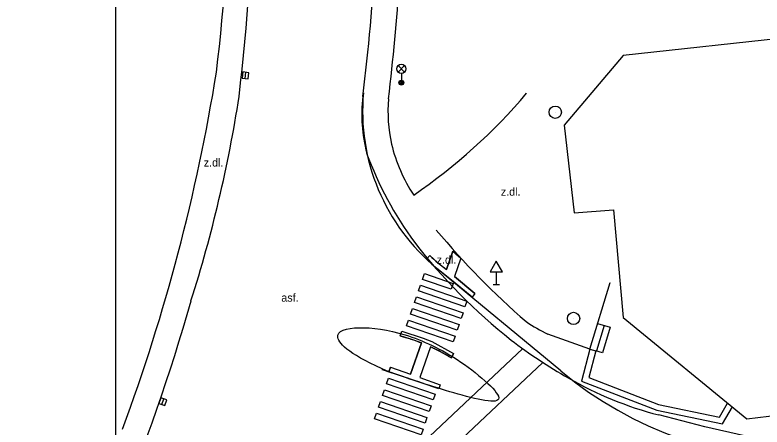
# Model space of a CAD drawing. Extents: x -438200 to -437954, y -1133133 to -1132850.
# Drawn here: x -438175.3 to -438114.6, y -1132947 to -1132913.5 of the extents above; entities that cross this region are included whole.
import ezdxf

# ---------------------------------------------------------------- set-up
doc = ezdxf.new("R2010")
doc.units = 0
for name, color, linetype in [('Vrstva 1', 7, 'Continuous'), ('Vrstva 10', 7, 'Continuous'), ('Vrstva 11', 7, 'Continuous'), ('Vrstva 15', 7, 'Continuous'), ('Vrstva 27', 7, 'Continuous'), ('Vrstva 33', 7, 'Continuous'), ('Vrstva 34', 7, 'Continuous'), ('Vrstva 40', 7, 'Continuous'), ('Vrstva 5', 7, 'Continuous'), ('Vrstva 7', 7, 'Continuous')]:
    doc.layers.add(name, color=color, linetype=linetype)

msp = doc.modelspace()

# ---------------------------------------------------------------- linework, layer by layer
at = {"layer": 'Vrstva 1'}
for p, q in [((-438167.156, -1132895.77), (-438167.156, -1133045.77)), ((-438167.156, -1132895.77), (-438167.156, -1133045.77)), ((-438158.957, -1132918.149), (-438158.957, -1132918.149)), ((-438156.595, -1132918.413), (-438156.595, -1132918.413)), ((-438143.939, -1132919.006), (-438143.939, -1132919.006)), ((-438157.116, -1132920.127), (-438157.116, -1132920.127)), ((-438147.07, -1132920.136), (-438147.07, -1132920.136)), ((-438133.765, -1132919.871), (-438133.765, -1132919.871)), ((-438144.985, -1132920.316), (-438144.985, -1132920.316)), ((-438131.431, -1132921.405), (-438131.431, -1132921.405)), ((-438130.7, -1132922.46), (-438130.7, -1132922.46)), ((-438144.742, -1132924.002), (-438144.742, -1132924.002)), ((-438137.844, -1132924.111), (-438137.844, -1132924.111)), ((-438146.757, -1132924.735), (-438146.757, -1132924.735)), ((-438142.935, -1132928.139), (-438142.935, -1132928.139)), ((-438126.705, -1132929.331), (-438126.705, -1132929.331)), ((-438144.335, -1132929.862), (-438144.335, -1132929.862)), ((-438129.914, -1132929.587), (-438129.914, -1132929.587)), ((-438141.101, -1132930.989), (-438141.101, -1132930.989)), ((-438142.882, -1132931.977), (-438142.882, -1132931.977)), ((-438130.987, -1132942.441), (-438141.071, -1132934.08)), ((-438130.987, -1132942.441), (-438141.071, -1132934.08)), ((-438136.224, -1132935.407), (-438136.224, -1132935.407)), ((-438126.979, -1132935.245), (-438126.979, -1132935.245)), ((-438139.671, -1132935.704), (-438139.671, -1132935.704)), ((-438136.973, -1132935.488), (-438136.973, -1132935.488)), ((-438161.028, -1132936.751), (-438161.028, -1132936.751)), ((-438133.787, -1132938.432), (-438133.787, -1132938.432)), ((-438129.95, -1132938.171), (-438129.95, -1132938.171)), ((-438125.927, -1132938.095), (-438125.927, -1132938.095)), ((-438126.976, -1132938.888), (-438126.976, -1132938.888)), ((-438132.039, -1132939.452), (-438132.039, -1132939.452)), ((-438135.02, -1132939.927), (-438135.02, -1132939.927)), ((-438128.639, -1132940.673), (-438128.639, -1132940.673)), ((-438130.379, -1132943.006), (-438130.379, -1132943.006)), ((-438129.292, -1132943.274), (-438129.292, -1132943.274)), ((-438163.315, -1132944.939), (-438163.315, -1132944.939)), ((-438127.076, -1132944.653), (-438127.076, -1132944.653)), ((-438123.197, -1132945.641), (-438123.197, -1132945.641)), ((-438123.021, -1132946.022), (-438123.021, -1132946.022)), ((-438115.881, -1132946.325), (-438115.881, -1132946.325)), ((-438117.845, -1132946.752), (-438117.845, -1132946.752)), ((-438119.29, -1132946.982), (-438119.29, -1132946.982))]:
    msp.add_line(p, q, dxfattribs=at)
for points in [[(-438139.753, -1132932.7), (-438139.103, -1132933.269), (-438139.616, -1132934.766), (-438137.962, -1132936.138), (-438138.18, -1132936.454), (-438139.738, -1132935.172), (-438141.071, -1132934.08), (-438141.908, -1132933.364), (-438141.626, -1132933.057), (-438140.995, -1132933.635), (-438140.269, -1132934.203)], [(-438139.753, -1132932.7), (-438139.103, -1132933.269), (-438139.616, -1132934.766), (-438137.962, -1132936.138), (-438138.18, -1132936.454), (-438139.738, -1132935.172), (-438141.071, -1132934.08), (-438141.908, -1132933.364), (-438141.626, -1132933.057), (-438140.995, -1132933.635), (-438140.269, -1132934.203)], [(-438142.23, -1132934.996), (-438142.068, -1132934.524), (-438139.738, -1132935.323), (-438139.901, -1132935.796)], [(-438142.23, -1132934.996), (-438142.068, -1132934.524), (-438139.738, -1132935.323), (-438139.901, -1132935.796)], [(-438142.555, -1132935.942), (-438142.393, -1132935.469), (-438138.612, -1132936.767), (-438138.775, -1132937.24)], [(-438142.555, -1132935.942), (-438142.393, -1132935.469), (-438138.612, -1132936.767), (-438138.775, -1132937.24)], [(-438142.879, -1132936.888), (-438142.717, -1132936.415), (-438138.926, -1132937.716), (-438139.089, -1132938.189)], [(-438142.879, -1132936.888), (-438142.717, -1132936.415), (-438138.926, -1132937.716), (-438139.089, -1132938.189)], [(-438143.204, -1132937.834), (-438143.042, -1132937.361), (-438139.242, -1132938.665), (-438139.404, -1132939.138)], [(-438143.204, -1132937.834), (-438143.042, -1132937.361), (-438139.242, -1132938.665), (-438139.404, -1132939.138)], [(-438143.529, -1132938.78), (-438143.366, -1132938.307), (-438139.564, -1132939.612), (-438139.727, -1132940.085)], [(-438143.529, -1132938.78), (-438143.366, -1132938.307), (-438139.564, -1132939.612), (-438139.727, -1132940.085)], [(-438145.149, -1132943.501), (-438144.986, -1132943.028), (-438141.204, -1132944.326), (-438141.366, -1132944.799)], [(-438145.149, -1132943.501), (-438144.986, -1132943.028), (-438141.204, -1132944.326), (-438141.366, -1132944.799)], [(-438145.473, -1132944.446), (-438145.311, -1132943.973), (-438141.529, -1132945.271), (-438141.691, -1132945.744)], [(-438145.473, -1132944.446), (-438145.311, -1132943.973), (-438141.529, -1132945.271), (-438141.691, -1132945.744)], [(-438145.798, -1132945.392), (-438145.636, -1132944.919), (-438141.856, -1132946.217), (-438142.018, -1132946.689)], [(-438145.798, -1132945.392), (-438145.636, -1132944.919), (-438141.856, -1132946.217), (-438142.018, -1132946.689)], [(-438146.122, -1132946.338), (-438145.96, -1132945.865), (-438142.177, -1132947.163), (-438142.339, -1132947.636)], [(-438146.122, -1132946.338), (-438145.96, -1132945.865), (-438142.177, -1132947.163), (-438142.339, -1132947.636)]]:
    msp.add_lwpolyline(points, close=True, dxfattribs=at)
for centre, radius, start, end in [((-438130.547, -1132921.319), 16.541, 174.80144, 230.49079), ((-438130.547, -1132921.319), 16.541, 174.80144, 230.49079), ((-438110.563, -1132917.807), 32, 230.33647, 309.11864), ((-438110.563, -1132917.807), 32, 230.33647, 309.11864)]:
    msp.add_arc(centre, radius, start, end, dxfattribs=at)
msp.add_open_spline([(-438144.958, -1132942.509), (-438148, -1132941.199), (-438149.996, -1132939.359), (-438147.626, -1132938.737), (-438143.739, -1132939.25), (-438139.185, -1132941.338), (-438134.209, -1132945.715), (-438140.218, -1132944.135), (-438144.958, -1132942.509), (-438146.526, -1132941.975), (-438142.582, -1132943.306)], degree=3, dxfattribs=at)
msp.add_open_spline([(-438144.958, -1132942.509), (-438148, -1132941.199), (-438149.996, -1132939.359), (-438147.626, -1132938.737), (-438143.739, -1132939.25), (-438139.185, -1132941.338), (-438134.209, -1132945.715), (-438140.218, -1132944.135), (-438144.958, -1132942.509), (-438146.526, -1132941.975), (-438142.582, -1132943.306)], degree=3, dxfattribs=at)
at = {"layer": 'Vrstva 10'}
for p, q in [((-438134.081, -1132940.629), (-438141.651, -1132947.764)), ((-438132.454, -1132941.746), (-438139.469, -1132948.358))]:
    msp.add_line(p, q, dxfattribs=at)
msp.add_lwpolyline([(-438095.924, -1132946.534), (-438105.196, -1132947.647), (-438110.044, -1132947.938), (-438116.055, -1132947.713), (-438119.29, -1132946.982), (-438123.021, -1132946.022)], dxfattribs=at)
for centre, radius, start, end in [((-438384.633, -1132894.507), 228.955, 353.57529, 2.49989), ((-438319.386, -1132898.79), 173.633, 352.93848, 0.58519), ((-438267.774, -1132902.859), 111.997, 342.38526, 351.13063), ((-438134.402, -1132921.584), 12.75, 173.47891, 194.30798), ((-438118.671, -1132914.365), 29.94, 200.26603, 216.03406), ((-438106.646, -1132904.004), 45.777, 217.66642, 231.69584), ((-438304.45, -1132896.337), 149.008, 330.05849, 344.26304), ((-438111.102, -1132908.912), 39.167, 232.36119, 240.51546), ((-438115.759, -1132917.821), 29.121, 239.86409, 255.55905)]:
    msp.add_arc(centre, radius, start, end, dxfattribs=at)
at = {"layer": 'Vrstva 11'}
for p, q in [((-438127.454, -1132938.742), (-438128.087, -1132940.815)), ((-438127.998, -1132938.576), (-438126.976, -1132938.888)), ((-438126.976, -1132938.888), (-438127.609, -1132940.961)), ((-438127.609, -1132940.961), (-438128.154, -1132940.795))]:
    msp.add_line(p, q, dxfattribs=at)
for points in [[(-438128.639, -1132940.673), (-438126.979, -1132935.245)], [(-438128.639, -1132940.673), (-438132.039, -1132939.452)]]:
    msp.add_lwpolyline(points, dxfattribs=at)
for centre, radius, start, end in [((-438353.312, -1132895.52), 195.668, 353.35896, 3.21989), ((-438315.621, -1132899.594), 171.89, 353.07606, 359.53813), ((-438312.067, -1132893.395), 155.099, 339.71616, 350.81615), ((-438168.696, -1132890.349), 45.735, 304.28128, 319.79662), ((-438132.457, -1132921.341), 12.57, 175.32209, 192.22146), ((-438132.131, -1132920.957), 12.973, 193.57537, 213.61507), ((-438092.402, -1132890.449), 63.365, 219.77595, 229.22236), ((-438125.547, -1132926.319), 14.65, 235.77473, 243.6961)]:
    msp.add_arc(centre, radius, start, end, dxfattribs=at)
at = {"layer": 'Vrstva 15'}
for p, q in [((-438139.753, -1132932.7), (-438140.269, -1132934.203)), ((-438139.753, -1132932.7), (-438140.269, -1132934.203)), ((-438141.626, -1132933.057), (-438141.908, -1132933.364)), ((-438141.626, -1132933.057), (-438141.908, -1132933.364)), ((-438139.103, -1132933.269), (-438139.616, -1132934.766)), ((-438139.103, -1132933.269), (-438139.616, -1132934.766)), ((-438137.962, -1132936.138), (-438139.616, -1132934.766)), ((-438137.962, -1132936.138), (-438139.616, -1132934.766)), ((-438137.962, -1132936.138), (-438138.18, -1132936.454)), ((-438137.962, -1132936.138), (-438138.18, -1132936.454)), ((-438144.026, -1132939.587), (-438143.892, -1132939.205)), ((-438144.026, -1132939.587), (-438143.892, -1132939.205)), ((-438142.312, -1132940.16), (-438143.188, -1132942.714)), ((-438142.312, -1132940.16), (-438143.188, -1132942.714)), ((-438141.574, -1132940.473), (-438142.434, -1132942.982)), ((-438141.574, -1132940.473), (-438142.434, -1132942.982)), ((-438139.864, -1132941.388), (-438139.696, -1132941.026)), ((-438139.864, -1132941.388), (-438139.696, -1132941.026)), ((-438144.829, -1132942.13), (-438144.958, -1132942.509)), ((-438144.829, -1132942.13), (-438144.958, -1132942.509)), ((-438144.829, -1132942.13), (-438143.188, -1132942.714)), ((-438144.829, -1132942.13), (-438143.188, -1132942.714)), ((-438142.434, -1132942.982), (-438140.785, -1132943.569)), ((-438142.434, -1132942.982), (-438140.785, -1132943.569)), ((-438140.785, -1132943.569), (-438140.891, -1132943.898)), ((-438140.785, -1132943.569), (-438140.891, -1132943.898))]:
    msp.add_line(p, q, dxfattribs=at)
msp.add_lwpolyline([(-438143.892, -1132939.205), (-438142.172, -1132939.775), (-438141.455, -1132940.057), (-438139.696, -1132941.026), (-438139.864, -1132941.388), (-438140.801, -1132940.849), (-438141.574, -1132940.473), (-438142.434, -1132942.982), (-438140.785, -1132943.569), (-438140.891, -1132943.898), (-438144.958, -1132942.509), (-438144.829, -1132942.13), (-438143.188, -1132942.714), (-438142.312, -1132940.16), (-438143.181, -1132939.847), (-438144.026, -1132939.587)], close=True, dxfattribs=at)
msp.add_lwpolyline([(-438143.892, -1132939.205), (-438142.172, -1132939.775), (-438141.455, -1132940.057), (-438139.696, -1132941.026), (-438139.864, -1132941.388), (-438140.801, -1132940.849), (-438141.574, -1132940.473), (-438142.434, -1132942.982), (-438140.785, -1132943.569), (-438140.891, -1132943.898), (-438144.958, -1132942.509), (-438144.829, -1132942.13), (-438143.188, -1132942.714), (-438142.312, -1132940.16), (-438143.181, -1132939.847), (-438144.026, -1132939.587)], close=True, dxfattribs=at)
for centre, start, end in [((-438128.804, -1132920.841), 227.28625, 230.3548), ((-438128.804, -1132920.841), 227.28625, 230.3548), ((-438130.547, -1132921.319), 226.65396, 232.96535), ((-438130.547, -1132921.319), 226.65396, 232.96535)]:
    msp.add_arc(centre, 16.141, start, end, dxfattribs=at)
for points, degree in [([(-438144.026, -1132939.587), (-438143.967, -1132939.604), (-438143.393, -1132939.773), (-438142.832, -1132939.956), (-438142.312, -1132940.16)], 3), ([(-438144.026, -1132939.587), (-438143.967, -1132939.604), (-438143.393, -1132939.773), (-438142.832, -1132939.956), (-438142.312, -1132940.16)], 3), ([(-438141.574, -1132940.473), (-438141.039, -1132940.717), (-438140.478, -1132941.013), (-438139.864, -1132941.388)], 2), ([(-438141.574, -1132940.473), (-438141.039, -1132940.717), (-438140.478, -1132941.013), (-438139.864, -1132941.388)], 2)]:
    msp.add_open_spline(points, degree=degree, dxfattribs=at)
at = {"layer": 'Vrstva 27'}
for p, q in [((-438156.625, -1132918.661), (-438156.565, -1132918.165)), ((-438163.392, -1132945.177), (-438163.238, -1132944.701))]:
    msp.add_line(p, q, dxfattribs=at)
for points in [[(-438156.376, -1132918.691), (-438156.317, -1132918.194), (-438156.814, -1132918.135), (-438156.873, -1132918.632)], [(-438163.154, -1132945.254), (-438163, -1132944.778), (-438163.476, -1132944.624), (-438163.63, -1132945.1)]]:
    msp.add_lwpolyline(points, close=True, dxfattribs=at)
for centre in [(-438131.431, -1132921.405), (-438129.95, -1132938.171)]:
    msp.add_circle(centre, 0.5, dxfattribs=at)
at = {"layer": 'Vrstva 33'}
for p, q in [((-438144.204, -1132918.146), (-438143.674, -1132917.616)), ((-438144.204, -1132917.616), (-438143.674, -1132918.146)), ((-438143.939, -1132918.256), (-438143.939, -1132919.006))]:
    msp.add_line(p, q, dxfattribs=at)
for centre, radius in [((-438143.939, -1132917.881), 0.375), ((-438143.939, -1132919.006), 0.2), ((-438143.939, -1132919.006), 0.145), ((-438143.939, -1132919.006), 0.0876)]:
    msp.add_circle(centre, radius, dxfattribs=at)
at = {"layer": 'Vrstva 34'}
for p, q in [((-438136.224, -1132934.389), (-438136.224, -1132935.407)), ((-438136.474, -1132935.407), (-438135.974, -1132935.407))]:
    msp.add_line(p, q, dxfattribs=at)
msp.add_lwpolyline([(-438136.724, -1132934.389), (-438135.724, -1132934.389), (-438136.224, -1132933.523)], close=True, dxfattribs=at)
at = {"layer": 'Vrstva 5'}
for p, q in [((-438130.7, -1132922.46), (-438129.914, -1132929.587)), ((-438129.914, -1132929.587), (-438126.705, -1132929.331)), ((-438126.705, -1132929.331), (-438125.927, -1132938.095)), ((-438125.927, -1132938.095), (-438115.881, -1132946.325)), ((-438115.881, -1132946.325), (-438103.779, -1132944.937))]:
    msp.add_line(p, q, dxfattribs=at)
msp.add_lwpolyline([(-438111.968, -1132915.287), (-438125.93, -1132916.81), (-438130.7, -1132922.46)], dxfattribs=at)
at = {"layer": 'Vrstva 7'}
for points in [[(-438128.639, -1132940.673), (-438129.292, -1132943.274), (-438123.197, -1132945.641), (-438117.845, -1132946.752), (-438117.048, -1132945.369)], [(-438128.154, -1132940.795), (-438128.7, -1132942.968), (-438123.055, -1132945.16), (-438118.098, -1132946.189), (-438117.44, -1132945.048)], [(-438128.639, -1132940.673), (-438128.154, -1132940.795)]]:
    msp.add_lwpolyline(points, dxfattribs=at)

# ---------------------------------------------------------------- texts
at = {"layer": 'Vrstva 40'}
for s, p in [('z.dl.', (-438159.99, -1132925.825)), ('z.dl.', (-438135.855, -1132928.195)), ('z.dl.', (-438141.07, -1132933.725)), ('asf.', (-438153.689, -1132936.808))]:
    msp.add_text(s, height=0.65, dxfattribs=at).set_placement(p)

doc.saveas('drawing.dxf')
